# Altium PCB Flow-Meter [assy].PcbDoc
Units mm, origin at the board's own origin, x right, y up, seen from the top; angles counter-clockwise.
Board outline 17 x 19 mm, 2 copper layers (Top Layer, Bottom Layer), stack 1.571 mm thick; 0 components, 7 nets, 0 pads, 0 vias.
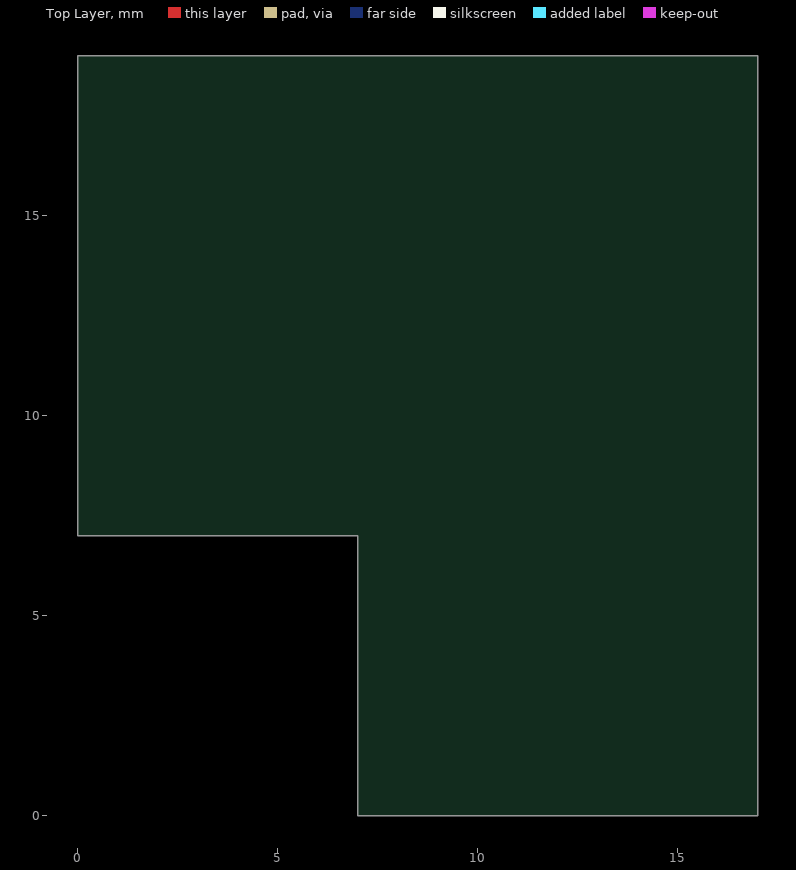
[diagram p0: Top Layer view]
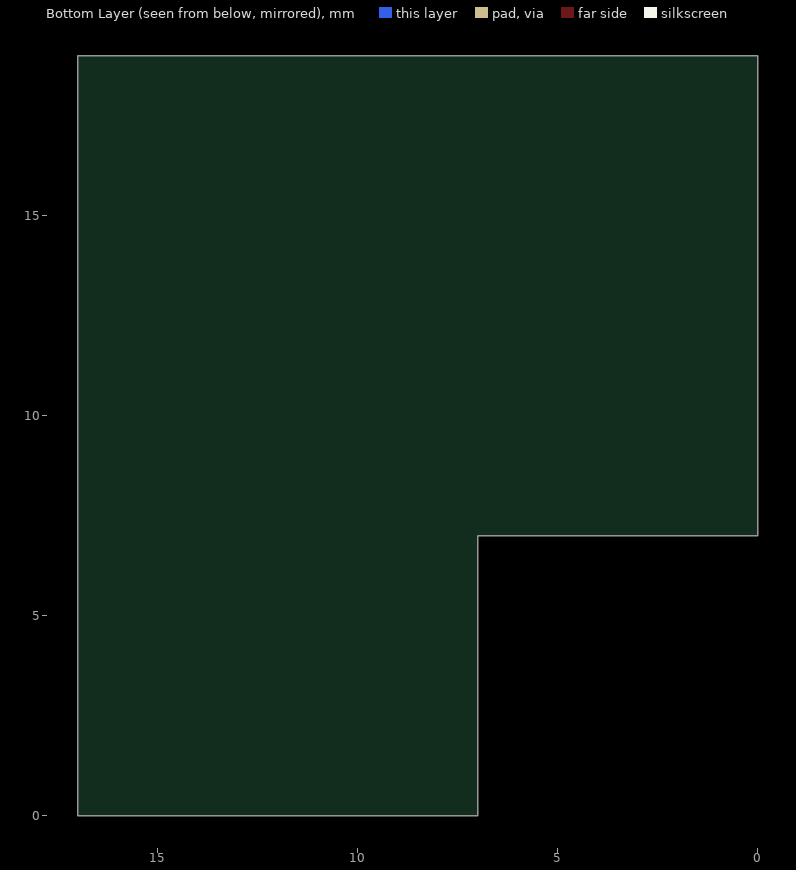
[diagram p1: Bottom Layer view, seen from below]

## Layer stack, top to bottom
Top Layer: signal copper 0.0356
Dielectric: prepreg 1.5, FR-4, Dk 4.2
Bottom Layer: signal copper 0.0356

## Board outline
0,7 0,19 17,19 17,0 7,0 7,7

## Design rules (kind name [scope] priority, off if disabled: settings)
Clearance [All] p1: gap=0.17
ComponentClearance [All] p1: gap=0 collisioncheckmode=3 verticalgap=0.025 showdistances=FALSE
FabricationTestPointUsage TestPointUsage [All] p1: valid=0 allowmultiple=FALSE
FabricationTestpoint Testpoint [All] p1: side=3 testpointundercomponent=TRUE minsize=1.016 maxsize=2.54 preferedsize=1.524 minholesize=0 maxholesize=1.016 preferedholesize=0.813 testpointgrid=0.025 allowsidetop=TRUE allowsidebottom=TRUE usegrid=TRUE gridtolerance=0
HoleSize [All] p1: absolutevalues=TRUE maxlimit=5 minlimit=0.25 maxpercent=80.000 minpercent=20.000
PlaneClearance [All] p1: clearance=0.5
PolygonConnect PolygonConnect_8 [All vs IsNamedPolygon('Top - GND1-HSK')] p1: connectstyle=Direct reliefconductorwidth=0.254 reliefentries=4 polygonreliefangle="90 Angle" airgapwidth=0.254
PolygonConnect PolygonConnect_7 [All vs IsNamedPolygon('Bot - GND1-HSK')] p2: connectstyle=Direct reliefconductorwidth=0.254 reliefentries=4 polygonreliefangle="90 Angle" airgapwidth=0.254
PolygonConnect PolygonConnect_6 [All vs IsNamedPolygon('Bot - GND4a') Or  IsNamedPolygon('Bot - GND2a') Or  IsNamedPolygon('Bot - GND3a')] p3: connectstyle=Direct reliefconductorwidth=0.254 reliefentries=4 polygonreliefangle="90 Angle" airgapwidth=0.254
PolygonConnect PolygonConnect_5 [All vs IsNamedPolygon('Bot - GND1a')] p4: connectstyle=Direct reliefconductorwidth=0.254 reliefentries=4 polygonreliefangle="90 Angle" airgapwidth=0.254
PolygonConnect PolygonConnectVia [All vs isvia] p5: connectstyle=Direct reliefconductorwidth=0.25 reliefentries=4 polygonreliefangle="90 Angle" airgapwidth=0.254
PolygonConnect PolygonConnect_4 [All vs IsNamedPolygon('Bot - GND2')] p6: connectstyle=Relief reliefconductorwidth=0.762 reliefentries=4 polygonreliefangle="90 Angle" airgapwidth=0.254
PolygonConnect PolygonConnect_3 [All vs IsNamedPolygon('Bot - GND1')] p7: connectstyle=Relief reliefconductorwidth=0.762 reliefentries=4 polygonreliefangle="90 Angle" airgapwidth=0.254
PolygonConnect PolygonConnect_2 [All vs IsNamedPolygon('Bot - GND4')] p8: connectstyle=Relief reliefconductorwidth=0.762 reliefentries=4 polygonreliefangle="90 Angle" airgapwidth=0.254
PolygonConnect PolygonConnect_1 [All vs IsNamedPolygon('Bot - GND3')] p9: connectstyle=Relief reliefconductorwidth=0.762 reliefentries=4 polygonreliefangle="90 Angle" airgapwidth=0.254
PolygonConnect [All] p10: connectstyle=Relief reliefconductorwidth=0.4 reliefentries=4 polygonreliefangle="90 Angle" airgapwidth=0.254
RoutingCorners [All] p1: cornerstyle=45-Degree minsetback=2.5 maxsetback=2.5
RoutingVias [All] p1: holewidth=0.3 width=0.7 viastyle="Through Hole" minholewidth=0.3 minwidth=0.7 maxholewidth=0.3 maxwidth=0.7
ShortCircuit ShortCircuit_LK1 [(InComponent('LK1'))] p1: allowed=TRUE
ShortCircuit ShortCircuit_LK2 [(InComponent('LK2'))] p2: allowed=TRUE
ShortCircuit ShortCircuit_LK3 [(InComponent('LK3'))] p3: allowed=TRUE
ShortCircuit [All] p4: allowed=FALSE
SilkToSolderMaskClearance SilkscreenOverComponentPads [IsPad] p1: minsilkscreentomaskgap=0.254 clearancetoexposedcopper=TRUE
SolderMaskExpansion [All] p1: expansion=0.05
Width "Width_High Power" [InNetClass('High Power')] p1: maxlimit=1.5 minlimit=0.5 preferedwidth=1
Width Width_Power [InNetClass('Power')] p2: maxlimit=1 minlimit=0.3 preferedwidth=0.5
Width [All] p3: maxlimit=2 minlimit=0.2 preferedwidth=0.2
20 further rules are at their usual default settings.

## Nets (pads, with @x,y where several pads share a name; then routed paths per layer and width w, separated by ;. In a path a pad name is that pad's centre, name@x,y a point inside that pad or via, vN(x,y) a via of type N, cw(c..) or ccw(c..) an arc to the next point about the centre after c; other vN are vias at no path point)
FLOW_METER: 
GND: 
NetD1_2: 
NetLK1_1: 
SCL: 
SDA: 
VI: 

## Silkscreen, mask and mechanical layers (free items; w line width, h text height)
Top Assy 1:
  circle w0.125: c0,0 r2
  lines w0.2: -110.84,-47.86 -53.84,-47.86 ; -98.34,-52.86 -98.34,-47.86 ; -53.84,-42.86 42.16,-42.86 133.16,-42.86 ; -53.84,-37.86 42.16,-37.86 ; -53.84,-32.86 42.16,-32.86 ; -53.84,-27.86 42.16,-27.86 ; -37.84,-52.86 -37.84,-22.86 ; -21.84,-22.86 -21.84,-52.86 -21.84,-47.86 ; -15,10 -13,10 ; -13,0 -15,0 -15,20 -13,20 ; -5.84,-52.86 -5.84,-22.86 ; -3,0 -1,0 ; 0,-13 0,-15 20,-15 20,-13 ; 0,-3 0,-1 ; 10,-15 10,-13 ; 10.16,-52.86 10.16,-22.86 ; 26.16,-52.86 26.16,-22.86 ; 60.16,-52.86 60.16,-42.86 ; 98.16,-52.86 98.16,-42.86 ; 111.16,-52.86 111.16,-42.86 ; 133.16,-47.86 42.16,-47.86 26.16,-47.86 10.16,-47.86 -5.84,-47.86 -21.84,-47.86 ; -53.84,-52.86 -53.84,-47.86 ; -53.84,-52.86 -53.84,-47.86 ; -53.84,-52.86 -53.84,-47.86 ; -53.84,-47.86 -53.84,-22.86 ; -53.84,-47.86 -37.84,-47.86 -21.84,-47.86 ; -53.84,-22.86 -69.84,-22.86 -110.84,-22.86 -110.84,-52.86 42.16,-52.86 ; -53.84,-22.86 42.16,-22.86 ; 42.16,-52.86 42.16,-22.86 ; 42.16,-52.86 133.16,-52.86 133.16,-22.86 42.16,-22.86
  text "20" at -12,19 h2.5
  text "10" at -12,9 h2.5
  text "0" at -12,-1 h2.5
  text "0" at 1,-12 h2.5 r90
  text "10" at 11,-12 h2.5 r90
  text "20" at 21,-12 h2.5 r90
  text "TITLE" at 44.16,-25.86 h2.5
  text "AGRIGEL" at -106.615,-32.284 h10
  text ".PCB_TITLE" at 47.16,-33.86 h5
  text "TOP SIDE PLACEMENT" at 47.16,-37.86 h2.5
  text ".PCB_Drawn" at -49.84,-45.86 h2.5
  text ".PCB_Checked" at -34.84,-45.86 h2.5
  text ".PCB_Approved" at -18.84,-45.86 h2.5
  text ".PRINT_DATE" at -2.84,-45.86 h2.5
  text ".PCB_DocRevision" at 11.16,-45.86 h2.5
  text ".PCB_ECRNo" at 30.16,-45.86 h2.5
  text "DWG NUMBER" at 43.16,-45.86 h2.5
  text ".PCB_Drawing Number" at 62.16,-45.86 h2.5
  text "PCB VER" at 99.16,-45.86 h2.5
  text "SHEET NO." at 113.16,-45.86 h2.5
  text "PLOTFILE" at -109.84,-50.86 h2.5
  text ".PCB_Plot File [Assy]" at -97.34,-50.86 h2.5
  text "DRAWN" at -49.84,-50.86 h2.5
  text "CHECKED" at -34.84,-50.86 h2.5
  text "APPROVED" at -19.84,-50.86 h2.5
  text "DATE" at -0.84,-50.86 h2.5
  text "DOC REV." at 13.16,-50.86 h2.5
  text "ECR NO." at 30.16,-50.86 h2.5
  text "SOURCE" at 43.16,-50.86 h2.5
  text ".Pcb_File_Name_No_Path" at 62.16,-50.86 h2.5
  text ".Version" at 101.16,-50.86 h2.5
  text "SHEET" at 113.16,-50.86 h2.5
  text "1" at 122.16,-50.86 h2.5
  text "OF" at 125.16,-50.86 h2.5
  text "2" at 130.16,-50.86 h2.5
Bot Assy 1:
  circle w0.125: c0,0 r2
  lines w0.2: -110.793,-47.907 -19.793,-47.907 -3.793,-47.907 12.207,-47.907 28.207,-47.907 44.207,-47.907 ; -110.793,-42.907 -19.793,-42.907 76.207,-42.907 ; -88.793,-52.907 -88.793,-42.907 ; -75.793,-52.907 -75.793,-42.907 ; -37.793,-52.907 -37.793,-42.907 ; -19.793,-37.907 76.207,-37.907 ; -19.793,-32.907 76.207,-32.907 ; -19.793,-27.907 76.207,-27.907 ; -15,10 -13,10 ; -13,0 -15,0 -15,20 -13,20 ; -3.793,-52.907 -3.793,-22.907 ; -3,0 -1,0 ; 0,-13 0,-15 20,-15 20,-13 ; 0,-3 0,-1 ; 10,-15 10,-13 ; 12.207,-52.907 12.207,-22.907 ; 28.207,-52.907 28.207,-22.907 ; 44.207,-22.907 44.207,-52.907 44.207,-47.907 ; 60.207,-52.907 60.207,-22.907 ; 120.707,-52.907 120.707,-47.907 ; 133.207,-47.907 76.207,-47.907 ; -19.793,-52.907 133.207,-52.907 133.207,-22.907 92.207,-22.907 76.207,-22.907 ; -19.793,-52.907 -19.793,-22.907 ; -19.793,-52.907 -110.793,-52.907 -110.793,-22.907 -19.793,-22.907 ; -19.793,-22.907 76.207,-22.907 ; 44.207,-47.907 60.207,-47.907 76.207,-47.907 ; 76.207,-52.907 76.207,-47.907 ; 76.207,-52.907 76.207,-47.907 ; 76.207,-52.907 76.207,-47.907 ; 76.207,-47.907 76.207,-22.907
  text "20" at -9.46,19 h2.5
  text "10" at -9.46,9 h2.5
  text "0" at -10.795,-1 h2.5
  text "10" at 11,-9.603 h2.5 r90
  text "20" at 21,-9.603 h2.5 r90
  text "0" at 1.015,-10.828 h2.5 r90
  text "TITLE" at -21.793,-25.907 h2.5
  text "AGRIGEL" at 128.935,-32.411 h10
  text ".PCB_TITLE" at -24.793,-33.907 h5
  text "BOTTOM SIDE PLACEMENT" at -24.793,-37.907 h2.5
  text "SHEET NO." at -90.793,-45.907 h2.5
  text "PCB VER" at -76.793,-45.907 h2.5
  text ".PCB_Drawing Number" at -39.793,-45.907 h2.5
  text "DWG NUMBER" at -20.793,-45.907 h2.5
  text ".PCB_ECRNo" at -7.793,-45.907 h2.5
  text ".PCB_DocRevision" at 11.207,-45.907 h2.5
  text ".PRINT_DATE" at 25.207,-45.907 h2.5
  text ".PCB_Approved" at 41.207,-45.907 h2.5
  text ".PCB_Checked" at 57.207,-45.907 h2.5
  text ".PCB_Drawn" at 72.207,-45.907 h2.5
  text "2" at -107.793,-50.907 h2.5
  text "OF" at -102.793,-50.907 h2.5
  text "2" at -99.793,-50.907 h2.5
  text "SHEET" at -90.793,-50.907 h2.5
  text ".Version" at -78.793,-50.907 h2.5
  text ".Pcb_File_Name_No_Path" at -39.793,-50.907 h2.5
  text "SOURCE" at -20.793,-50.907 h2.5
  text "ECR NO." at -7.793,-50.907 h2.5
  text "DOC REV." at 9.207,-50.907 h2.5
  text "DATE" at 23.207,-50.907 h2.5
  text "APPROVED" at 42.207,-50.907 h2.5
  text "CHECKED" at 57.207,-50.907 h2.5
  text "DRAWN" at 72.207,-50.907 h2.5
  text ".PCB_Plot File [Assy]" at 119.707,-50.907 h2.5
  text "PLOTFILE" at 132.207,-50.907 h2.5

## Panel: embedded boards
"Flow-Meter.PcbDoc" at 0,0, 1 rows x 1 columns, spacing 21.54 x 19.54, rotation 0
